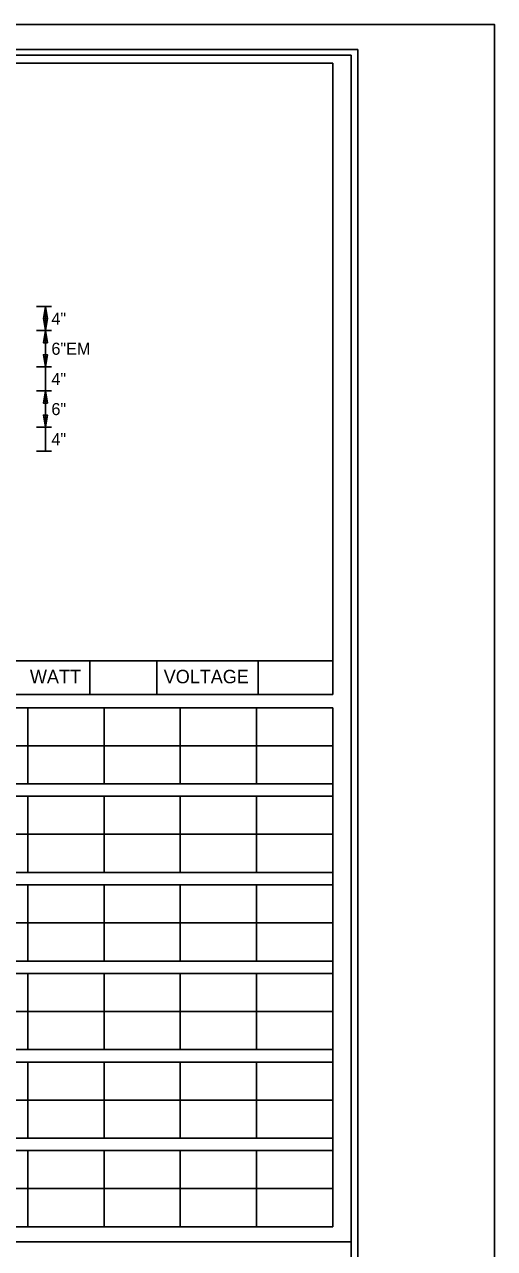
# Model space of a CAD drawing. Extents: x 1374 to 1480, y 568 to 638.
# Drawn here: x 1450.16 to 1456.65, y 587.74 to 604.64 of the extents above; entities that cross this region are included whole.
import ezdxf

# ---------------------------------------------------------------- set-up
doc = ezdxf.new("R2010")
doc.units = 0
for name, color, linetype in [('GSDims', 7, 'Continuous'), ('PlotBorder_dp', 7, 'Continuous'), ('SheetBorder_dp', 7, 'Continuous'), ('SheetLinesMisc2_dp', 7, 'Continuous'), ('TextMinor', 7, 'Continuous')]:
    doc.layers.add(name, color=color, linetype=linetype)

msp = doc.modelspace()

# ---------------------------------------------------------------- linework, layer by layer
at = {"layer": 'GSDims'}
for p, q in [((1450.323, 600.75), (1450.531, 600.75)), ((1450.323, 600.75), (1450.323, 600.75)), ((1450.448, 600.416), (1450.448, 600.75)), ((1450.323, 600.416), (1450.531, 600.416)), ((1450.323, 600.416), (1450.531, 600.416)), ((1450.448, 600.416), (1450.448, 599.916)), ((1450.323, 599.916), (1450.531, 599.916)), ((1450.323, 599.916), (1450.531, 599.916)), ((1450.448, 599.583), (1450.448, 599.916)), ((1450.323, 599.583), (1450.531, 599.583)), ((1450.323, 599.583), (1450.531, 599.583)), ((1450.448, 599.583), (1450.448, 599.083)), ((1450.323, 599.083), (1450.531, 599.083)), ((1450.323, 599.083), (1450.531, 599.083)), ((1450.448, 598.75), (1450.448, 599.083)), ((1450.323, 598.75), (1450.531, 598.75)), ((1450.323, 598.75), (1450.323, 598.75))]:
    msp.add_line(p, q, dxfattribs=at)
for points in [[(1450.448, 600.75), (1450.42, 600.583), (1450.476, 600.583)], [(1450.448, 600.416), (1450.42, 600.583), (1450.476, 600.583)], [(1450.448, 600.416), (1450.42, 600.249), (1450.476, 600.249)], [(1450.448, 599.916), (1450.42, 600.083), (1450.476, 600.083)], [(1450.448, 599.583), (1450.42, 599.416), (1450.476, 599.416)], [(1450.448, 599.083), (1450.42, 599.249), (1450.476, 599.249)]]:
    msp.add_lwpolyline(points, close=True, dxfattribs=at)
at = {"layer": 'PlotBorder_dp'}
msp.add_lwpolyline([(1400.035, 568.275), (1456.648, 568.275), (1456.648, 604.644), (1400.035, 604.644)], close=True, dxfattribs=at)
at = {"layer": 'SheetBorder_dp'}
for p, q in [((1401.922, 604.301), (1454.76, 604.301)), ((1454.76, 604.301), (1454.76, 568.618))]:
    msp.add_line(p, q, dxfattribs=at)
at = {"layer": 'SheetLinesMisc2_dp'}
for p, q in [((1402.016, 604.22), (1454.669, 604.22)), ((1436.509, 604.111), (1454.417, 604.111)), ((1454.417, 595.388), (1454.417, 604.111)), ((1454.669, 571.444), (1454.669, 604.22)), ((1436.509, 595.855), (1454.417, 595.855)), ((1451.062, 595.855), (1451.062, 595.388)), ((1451.988, 595.855), (1451.988, 595.388)), ((1453.383, 595.855), (1453.383, 595.388)), ((1436.509, 595.388), (1454.417, 595.388)), ((1428.522, 595.208), (1454.417, 595.208)), ((1450.203, 595.208), (1450.203, 594.156)), ((1451.257, 595.208), (1451.257, 594.156)), ((1452.31, 595.208), (1452.31, 594.156)), ((1453.364, 595.208), (1453.364, 594.156)), ((1454.417, 588.039), (1454.417, 595.208)), ((1428.522, 594.682), (1454.417, 594.682)), ((1428.522, 594.156), (1454.417, 594.156)), ((1428.522, 593.985), (1454.417, 593.985)), ((1450.203, 593.985), (1450.203, 592.933)), ((1451.257, 593.985), (1451.257, 592.933)), ((1452.31, 593.985), (1452.31, 592.933)), ((1453.364, 593.985), (1453.364, 592.933)), ((1428.522, 593.459), (1454.417, 593.459)), ((1428.522, 592.933), (1454.417, 592.933)), ((1428.522, 592.761), (1454.417, 592.761)), ((1450.203, 592.761), (1450.203, 591.709)), ((1451.257, 592.761), (1451.257, 591.709)), ((1452.31, 592.761), (1452.31, 591.709)), ((1453.364, 592.761), (1453.364, 591.709)), ((1428.522, 592.235), (1454.417, 592.235)), ((1428.522, 591.709), (1454.417, 591.709)), ((1428.522, 591.538), (1454.417, 591.538)), ((1450.203, 591.538), (1450.203, 590.486)), ((1451.257, 591.538), (1451.257, 590.486)), ((1452.31, 591.538), (1452.31, 590.486)), ((1453.364, 591.538), (1453.364, 590.486)), ((1428.522, 591.012), (1454.417, 591.012)), ((1428.522, 590.486), (1454.417, 590.486)), ((1428.522, 590.314), (1454.417, 590.314)), ((1450.203, 590.314), (1450.203, 589.262)), ((1451.257, 590.314), (1451.257, 589.262)), ((1452.31, 590.314), (1452.31, 589.262)), ((1453.364, 590.314), (1453.364, 589.262)), ((1428.522, 589.788), (1454.417, 589.788)), ((1428.522, 589.262), (1454.417, 589.262)), ((1428.522, 589.09), (1454.417, 589.09)), ((1450.203, 589.09), (1450.203, 588.039)), ((1451.257, 589.09), (1451.257, 588.039)), ((1452.31, 589.09), (1452.31, 588.039)), ((1453.364, 589.09), (1453.364, 588.039)), ((1428.522, 588.565), (1454.417, 588.565)), ((1428.522, 588.039), (1454.417, 588.039)), ((1402.016, 587.832), (1454.669, 587.832))]:
    msp.add_line(p, q, dxfattribs=at)

# ---------------------------------------------------------------- texts
at = {"layer": 'GSDims'}
for s, p in [('4"', (1450.531, 600.499)), ('6"EM', (1450.531, 600.083)), ('4"', (1450.531, 599.666)), ('6"', (1450.531, 599.249)), ('4"', (1450.531, 598.833))]:
    msp.add_text(s, height=0.1667, dxfattribs=at).set_placement(p)
at = {"layer": 'TextMinor'}
for s, p in [('WATT', (1450.234, 595.545)), ('VOLTAGE', (1452.081, 595.545))]:
    msp.add_text(s, height=0.186, dxfattribs=at).set_placement(p)

doc.saveas('drawing.dxf')
